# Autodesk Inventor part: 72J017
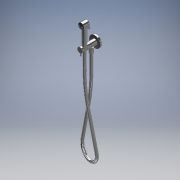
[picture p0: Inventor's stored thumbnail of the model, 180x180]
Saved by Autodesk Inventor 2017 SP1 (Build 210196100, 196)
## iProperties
Created: 2019-06
Part Number: 72J017
Material: Generico
Document SubType Name: Modeling
Designer: CIANI
Mass: 395.191 g
Surface Area: 926.303 cm^2
Volume: 395.191 cm^3
Density: 1 g/cm^3
Appearance: Cromo - Lucidato
Author: CIANI
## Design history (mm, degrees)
feature "Base3"
node "Solido1"
node "Solido4"
